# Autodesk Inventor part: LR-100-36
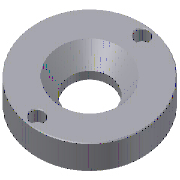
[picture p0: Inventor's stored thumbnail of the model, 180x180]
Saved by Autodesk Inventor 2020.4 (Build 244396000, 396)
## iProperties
IsCustomPart: 1
Created: 2019-01
Part Number: LR-100-36
Material: S 45 C
Description: Locating Ring
Document SubType Name: Modeling
Designer: mel
Standard Revision: 1
Manufacturer: LKM
Language: fr-FR
Size Designation: LR-100-36
Categories: <MemberInstance><Categories><Category DisplayName="Moule" InternalName="349578f2-f4d4-4954-8c09-8e99297a61c0" Mnemonic="MOLD"><Category DisplayName="Centrage" I
Mass: 93.9026 g
Surface Area: 200.182 cm^2
Volume: 93.9026 cm^3
Density: 7.85 g/cm^3
Appearance: Aluminium - Noir
Author: mel
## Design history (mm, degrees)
sketch "Sketch1"
  geometry: L1 (0, -3)-(0, 18) reference; L2 (28, 15)-(18, 5); L3 (18, 5)-(18, 0); L4 (18, 0)-(50, 0); L5 (50, 0)-(50, 15); L6 (50, 15)-(28, 15); 1 further point
  constraints: 10 end point, 2 horizontal, 2 vertical, 1 point on line
  dimensions: "d0" = 36 diameter of L3 L1 (= d_); "d1" = 45 deg angle of L1 L2; "d2" = 15 distance between parallel lines of L4 L6 (= T_); "d3" = 100 diameter of L5 L1 (= D); "d4" = 5 distance from line of L4 L2.end
revolve "Revolution1" sketch "Sketch1" stored, may be unused: angle "d5" = 90 deg
sketch "Sketch2"
  geometry: 3 further points
  constraints: 2 vertical alignment
  dimensions: "d26" = 42.5 distance of point (0, 0) point (0, 42.5) (= 0.5 x P); "d27" = 42.5 distance of point (0, -42.5) point (0, 0) (= 0.5 x P)
hole "Hole1" sketch "Sketch2" diameter "d7" = 6.6; stored, may be unused: countersink angle "d11" = 90 deg, drill point angle "d13" = 0 deg; dims "d8" = 6, "d9" = 11, "d10" = 6.8, "d12" = 15 (= T_)
hole "Hole2" sketch "Sketch2" diameter "d28" = 6.6; stored, may be unused: countersink angle "d32" = 90 deg, drill point angle "d34" = 0 deg; dims "d29" = 6, "d30" = 11, "d31" = 6.8, "d33" = 15 (= T_)
chamfer "Chamfer1" distance "d14" = 0.5; stored, may be unused: second distance "d15" = 2, angle "d16" = 45 deg
sketch "Sketch3"
  geometry: L1 (0, -3)-(0, 18) reference; L2 (0, 0)-(50, 0); L3 (50, 0)-(50, 15); L4 (50, 15)-(0, 15); L5 (0, 15)-(0, 0)
  constraints: 8 end point, 2 parallel, 1 horizontal, 1 perpendicular
  dimensions: "d20" = 100 diameter of L3 L1 (= D_CS); "d21" = 15 distance between parallel lines of L2 L4 (= T_CS)
feature "RevolutionSrf1" sketch "Sketch3" dims angle "d22" = 90 deg
body "Solid1"
body "Srf1"
other parameters: "D" = 100 [user parameter; used in 1 equation term], "d_" = 36 [user parameter; used in 1 equation term], "P" = 85 [user parameter; used in 2 equation terms], "T_" = 15 [user parameter; used in 3 equation terms], "D_CS" = 100 [user parameter; used in 1 equation term], "T_CS" = 15 [user parameter; used in 1 equation term], "d23" = 0, "d24" = 0, "d25" = 0
